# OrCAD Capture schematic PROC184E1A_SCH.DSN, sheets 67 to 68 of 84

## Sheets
67 72. POWER SUPPLY #1: size C; title: POWER SUPPLY #1; note: PROC184_SCH
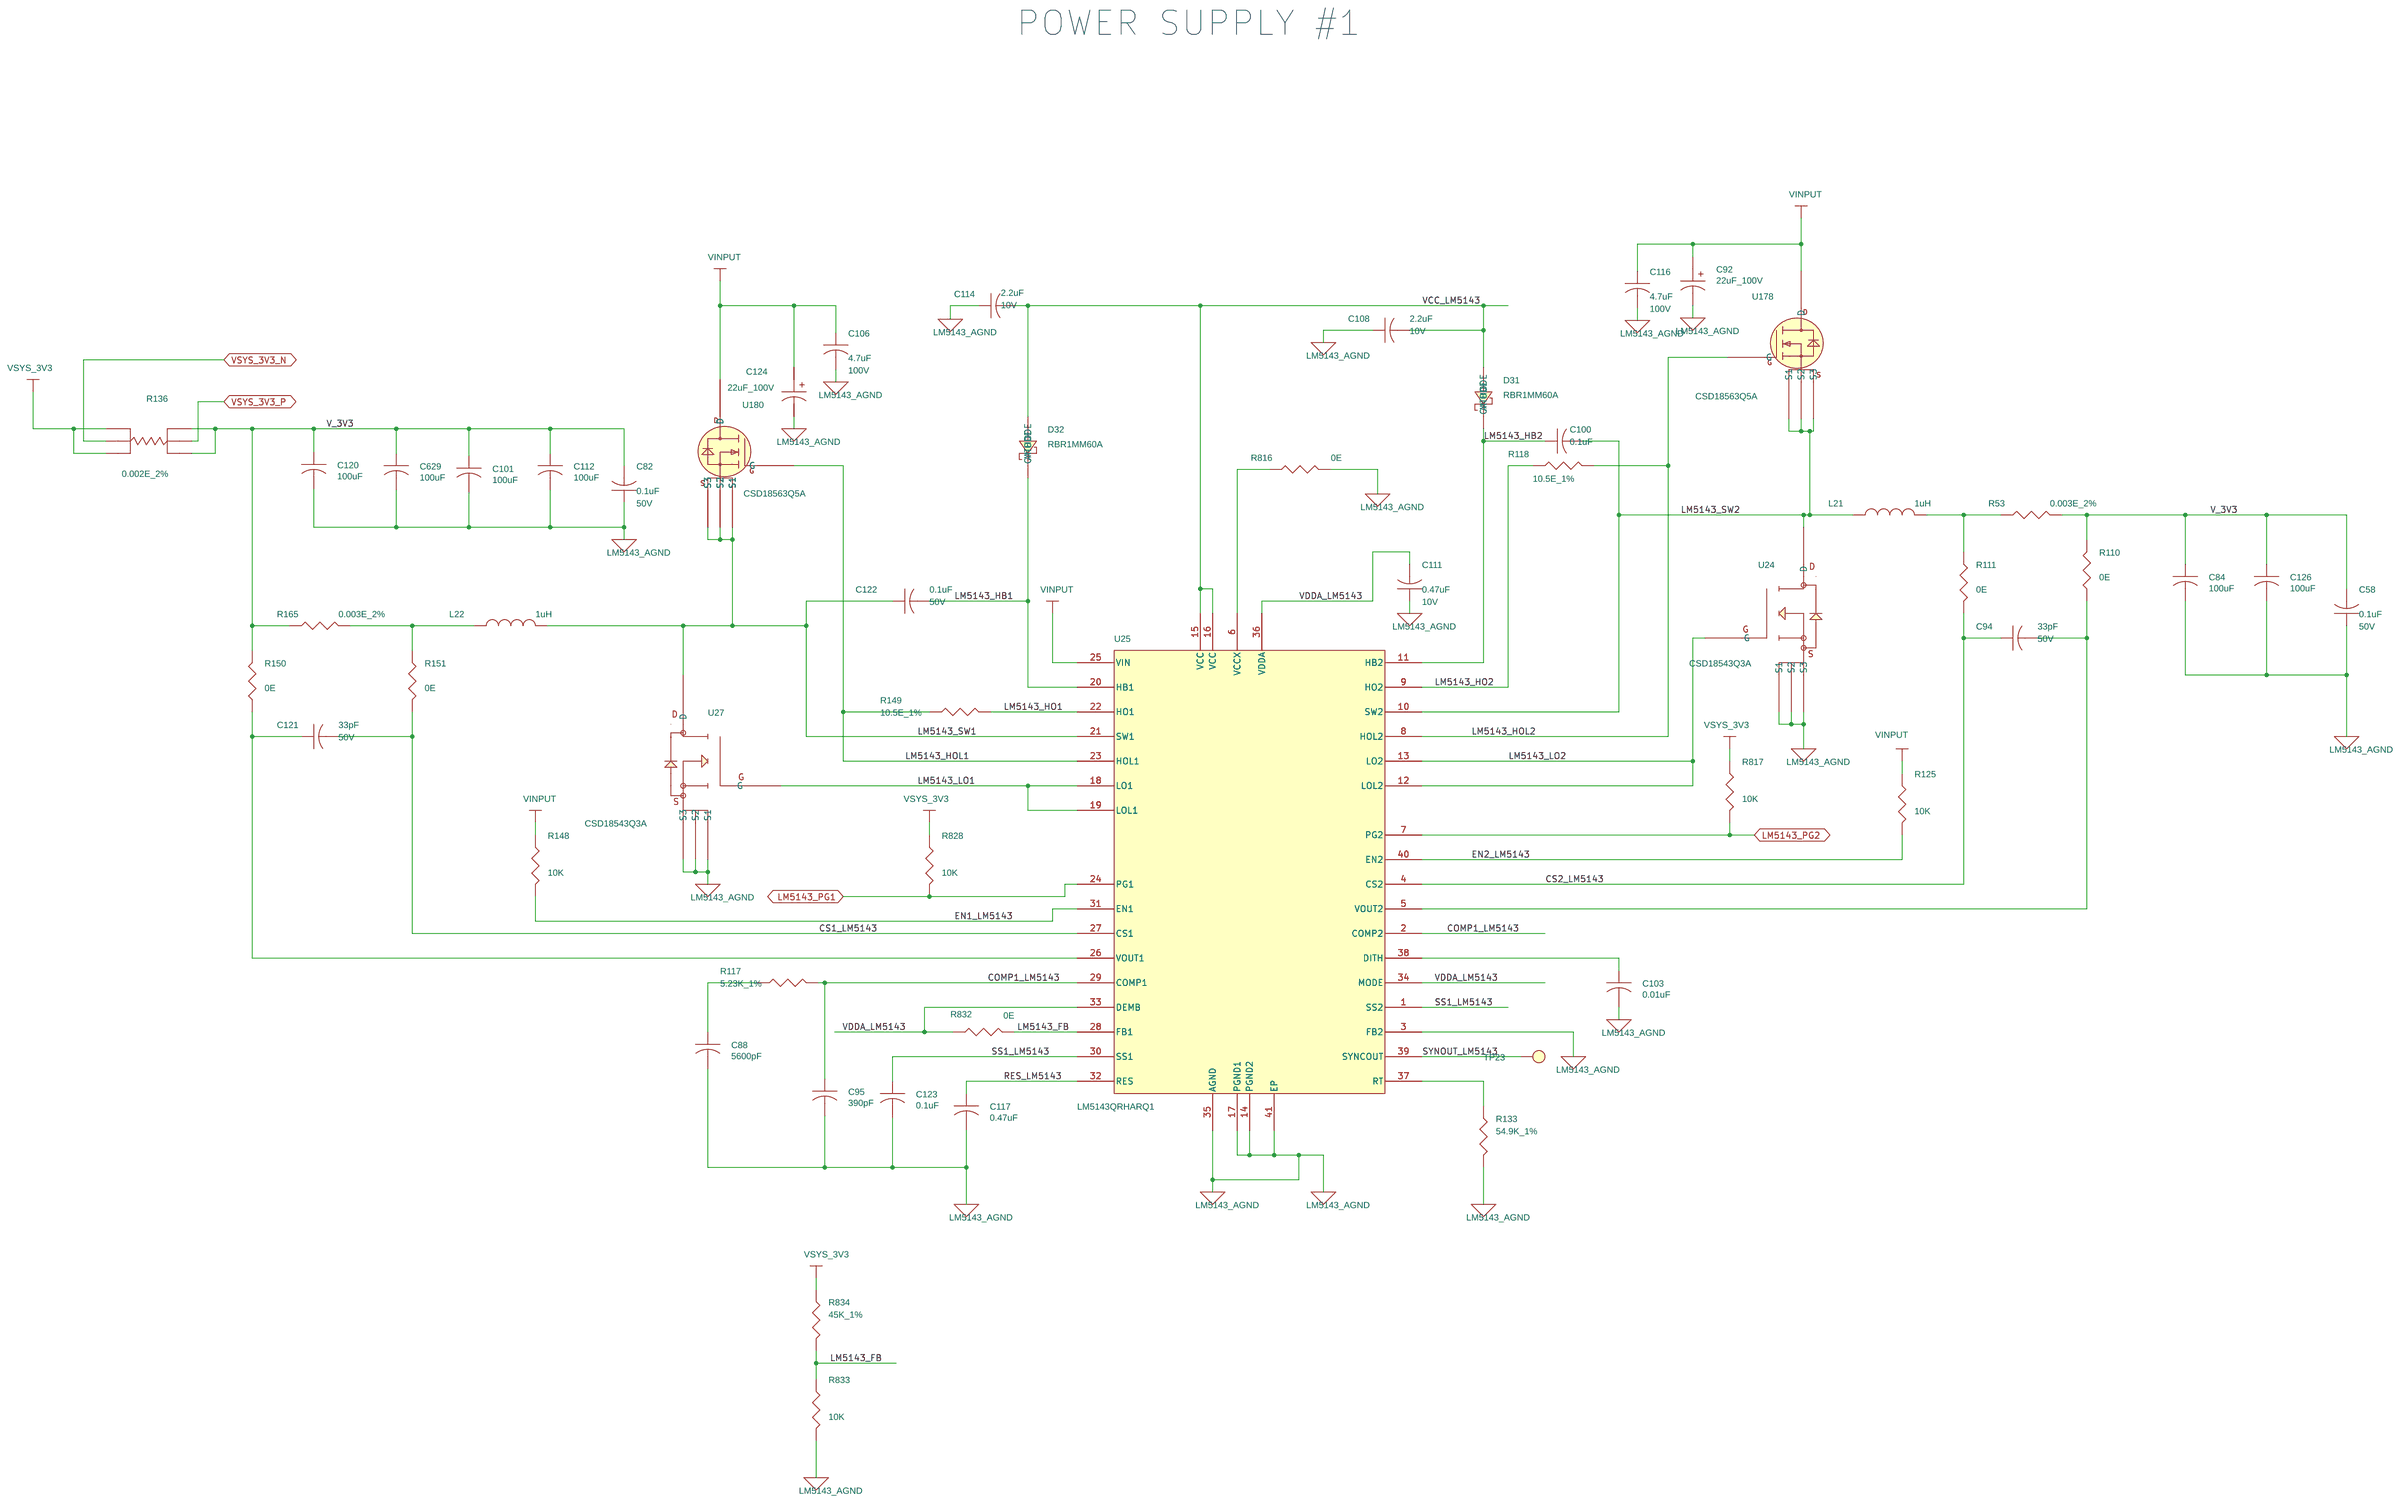
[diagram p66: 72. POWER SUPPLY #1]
68 75. POWER SUPPLY #4: size C; title: POWER SUPPLY #4; note: PROC184_SCH
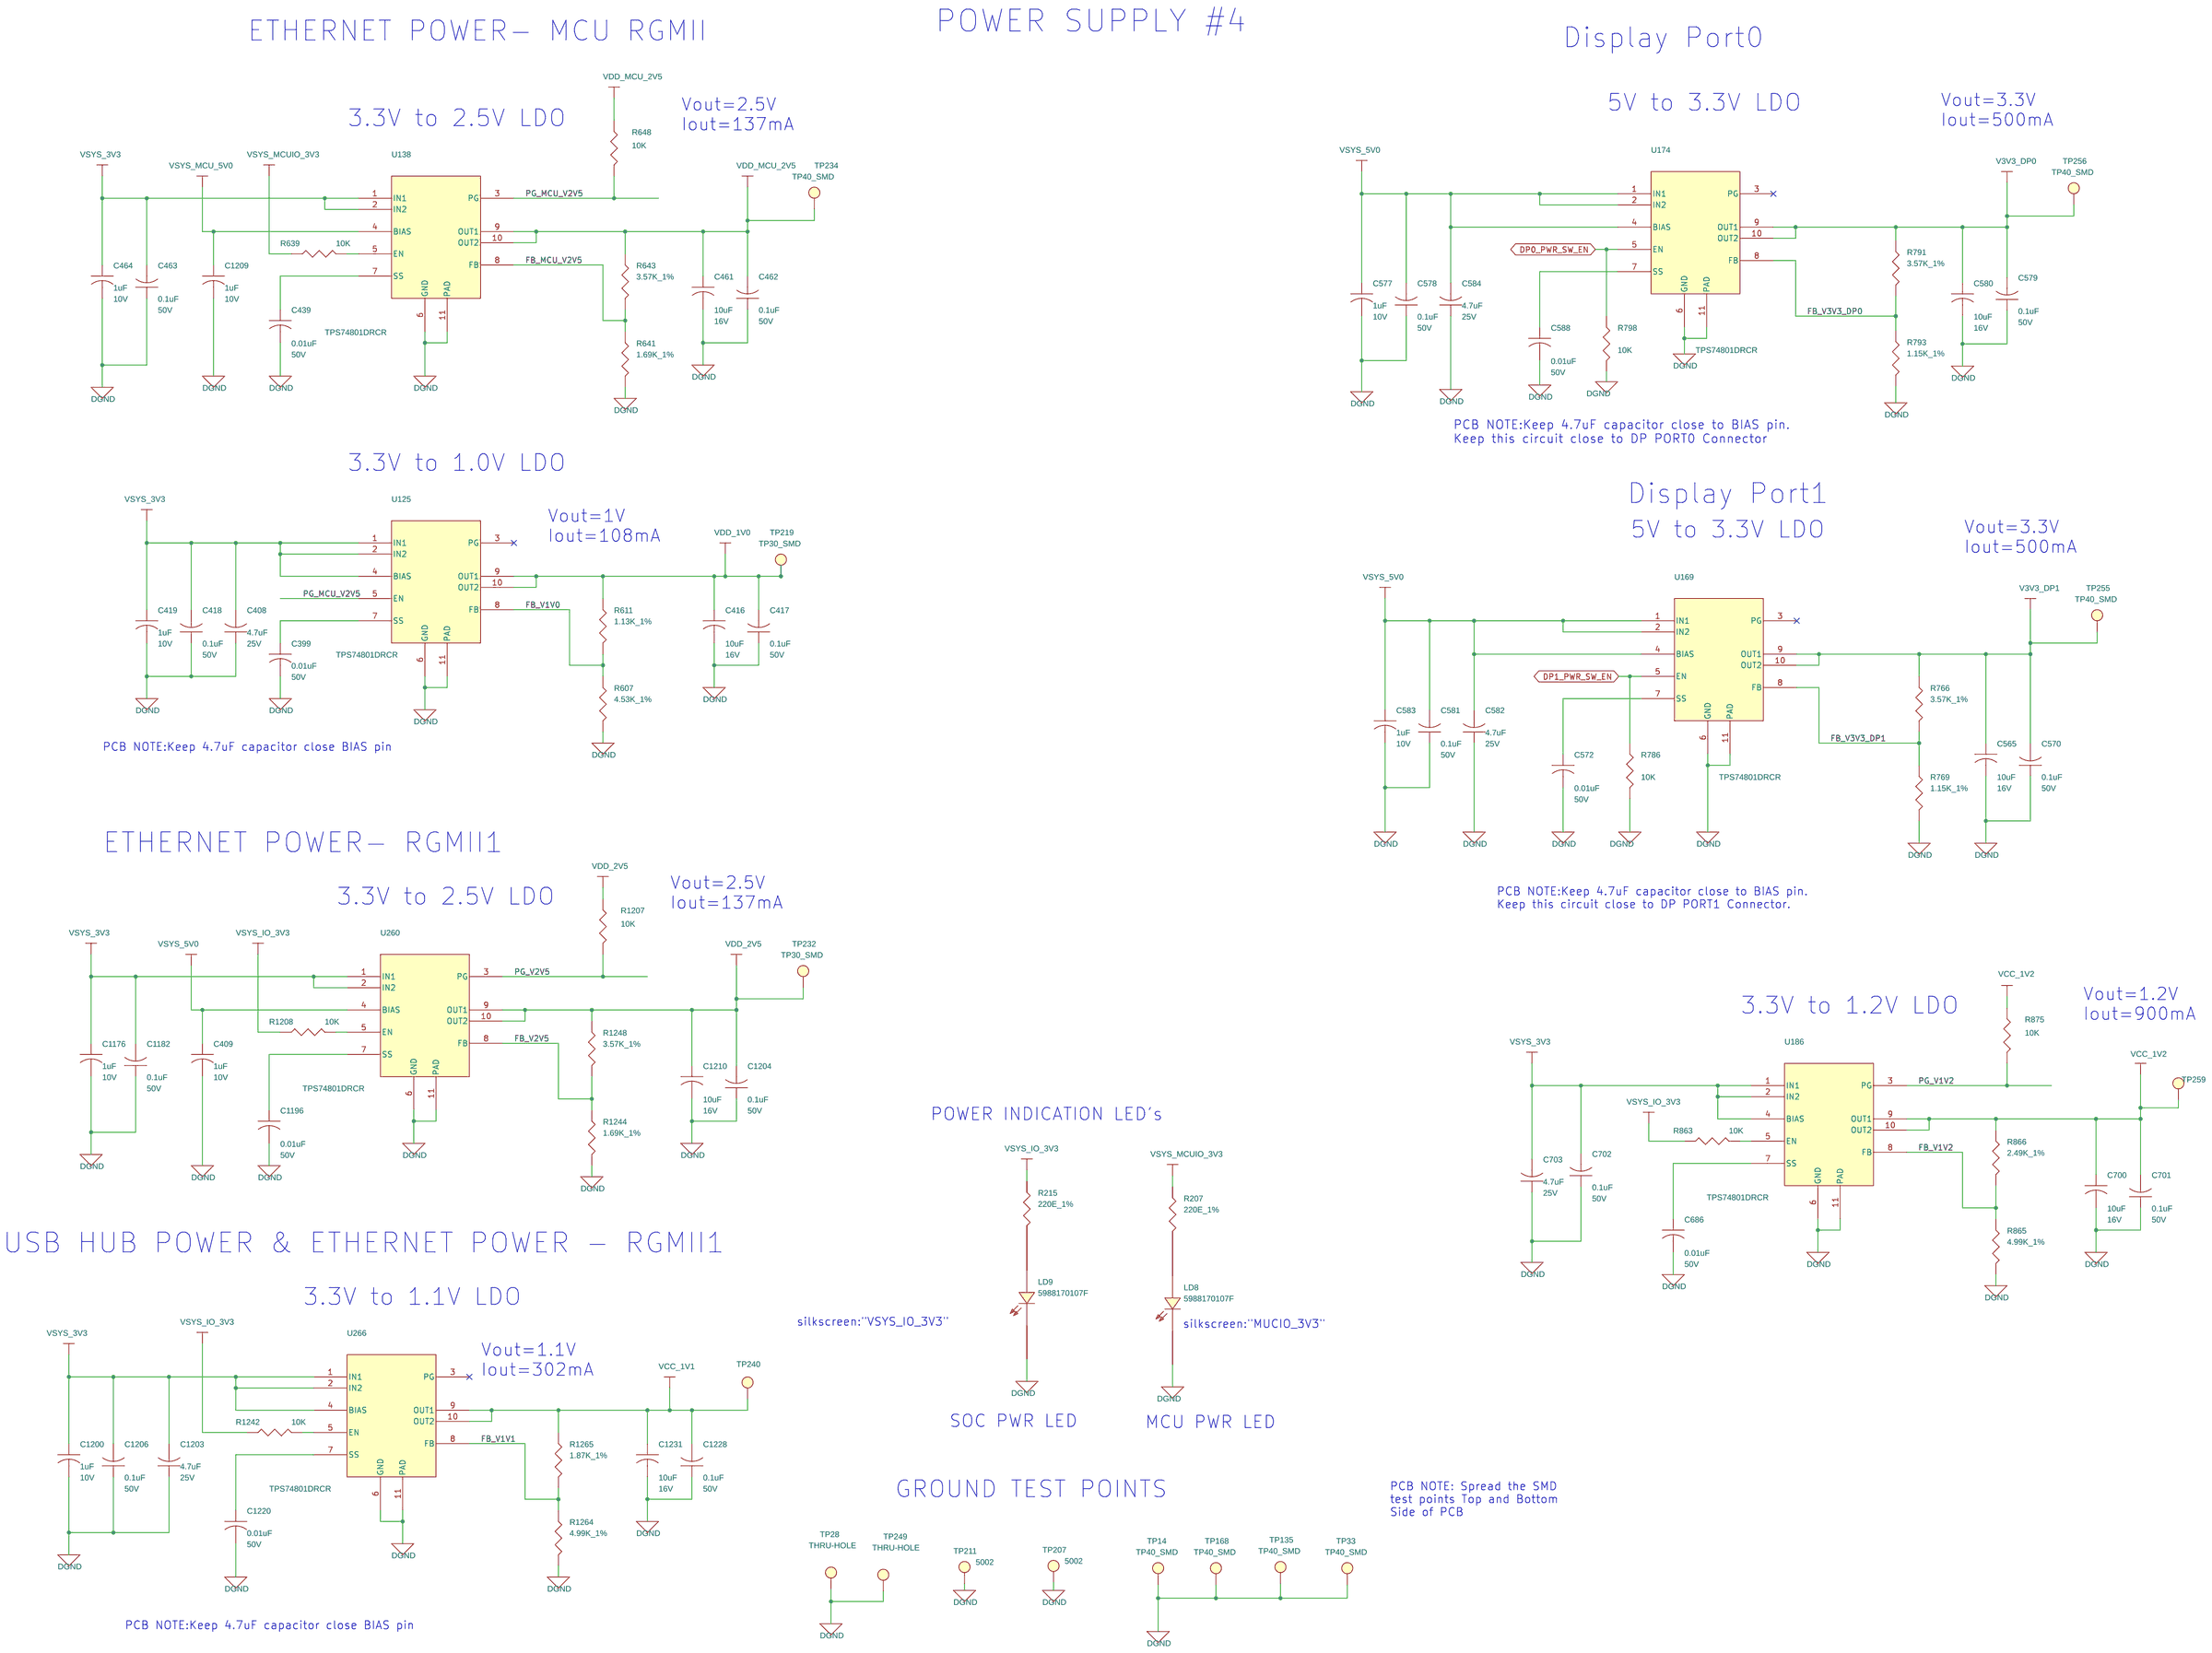
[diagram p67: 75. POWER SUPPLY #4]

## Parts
sheet 72. POWER SUPPLY #1
C58  0.1uF  [CAP0402_0-75]
C82  0.1uF  [CAP0402_0-75]
C84  100uF  [CAP1210_2-75]
C88  5600pF  [CAP0402_0-75]
C92  22uF_100V  [CAPAE_CASE8383_10-5]
C94  33pF  [CAP0402_0-75]
C95  390pF  [CAP0402_0-75]
C100  0.1uF  [CAP0402_0-75]
C101  100uF  [CAP1210_2-75]
C103  0.01uF  [CAP0402_0-75]
C106  4.7uF  [CAP1206_2]
C108  2.2uF  [CAP0402_0-75]
C111  0.47uF  [CAP0402_0-75]
C112  100uF  [CAP1210_2-75]
C114  2.2uF  [CAP0402_0-75]
C116  4.7uF  [CAP1206_2]
C117  0.47uF  [CAP0402_0-75]
C120  100uF  [CAP1210_2-75]
C121  33pF  [CAP0402_0-75]
C122  0.1uF  [CAP0402_0-75]
C123  0.1uF  [CAP0402_0-75]
C124  22uF_100V  [CAPAE_CASE8383_10-5]
C126  100uF  [CAP1210_2-75]
C629  100uF  [CAP1210_2-75]
D31  RBR1MM60A  [DIO_SOD123F_0-9]
D32  RBR1MM60A  [DIO_SOD123F_0-9]
L21  1uH  [IND_HLP5050CE-1R0-01_530X510_SMD_3-5]
L22  1uH  [IND_HLP5050CE-1R0-01_530X510_SMD_3-5]
R53  0.003E_2%  [RES1206_W_0-75]
R110  0E  [RES0402_0-5]
R111  0E  [RES0402_0-5]
R117  5.23K_1%  [RES0402_0-5]
R118  10.5E_1%  [RES0402_0-5]
R125  10K  [RES0402_0-5]
R133  54.9K_1%  [RES0402_0-5]
R136  0.002E_2%  [RES_FCSL90_3518-6_0-5_TI]
R148  10K  [RES0402_0-5]
R149  10.5E_1%  [RES0402_0-5]
R150  0E  [RES0402_0-5]
R151  0E  [RES0402_0-5]
R165  0.003E_2%  [RES1206_W_0-75]
R816  0E  [RES0402_0-5]
R817  10K  [RES0402_0-5]
R828  10K  [RES0402_0-5]
R832  0E  [RES0402_0-5]
R833  10K  [RES0402_0-5]
R834  45K_1%  [RES0402_0-5]
TP23  TP30_SMD  [TP30_SMD]
U24  CSD18543Q3A  [VSONP8_CSD18543Q_120X130_0-9]
U25  LM5143QRHARQ1  [QFN40_19-68_240X240_1_EP3-4]
U27  CSD18543Q3A  [VSONP8_CSD18543Q_120X130_0-9]
U178  CSD18563Q5A  [VSONP8_CSD19531_230X200_1-1]
U180  CSD18563Q5A  [VSONP8_CSD19531_230X200_1-1]
sheet 75. POWER SUPPLY #4
C399  0.01uF  [CAP0402_0-75]
C408  4.7uF  [CAP0603_1]
C409  1uF  [CAP0402_0-75]
C416  10uF  [CAP0805_1-5]
C417  0.1uF  [CAP0402_0-75]
C418  0.1uF  [CAP0402_0-75]
C419  1uF  [CAP0402_0-75]
C439  0.01uF  [CAP0402_0-75]
C461  10uF  [CAP0805_1-5]
C462  0.1uF  [CAP0402_0-75]
C463  0.1uF  [CAP0402_0-75]
C464  1uF  [CAP0402_0-75]
C565  10uF  [CAP0805_1-5]
C570  0.1uF  [CAP0402_0-75]
C572  0.01uF  [CAP0402_0-75]
C577  1uF  [CAP0402_0-75]
C578  0.1uF  [CAP0402_0-75]
C579  0.1uF  [CAP0402_0-75]
C580  10uF  [CAP0805_1-5]
C581  0.1uF  [CAP0402_0-75]
C582  4.7uF  [CAP0603_1]
C583  1uF  [CAP0402_0-75]
C584  4.7uF  [CAP0603_1]
C588  0.01uF  [CAP0402_0-75]
C686  0.01uF  [CAP0402_0-75]
C700  10uF  [CAP0805_1-5]
C701  0.1uF  [CAP0402_0-75]
C702  0.1uF  [CAP0402_0-75]
C703  4.7uF  [CAP0603_1]
C1176  1uF  [CAP0402_0-75]
C1182  0.1uF  [CAP0402_0-75]
C1196  0.01uF  [CAP0402_0-75]
C1200  1uF  [CAP0402_0-75]
C1203  4.7uF  [CAP0603_1]
C1204  0.1uF  [CAP0402_0-75]
C1206  0.1uF  [CAP0402_0-75]
C1209  1uF  [CAP0402_0-75]
C1210  10uF  [CAP0805_1-5]
C1220  0.01uF  [CAP0402_0-75]
C1228  0.1uF  [CAP0402_0-75]
C1231  10uF  [CAP0805_1-5]
LD8  5988170107F  [LED_0805_0-7]
LD9  5988170107F  [LED_0805_0-7]
R207  220E_1%  [RES0402_0-5]
R215  220E_1%  [RES0402_0-5]
R607  4.53K_1%  [RES0402_0-5]
R611  1.13K_1%  [RES0402_0-5]
R639  10K  [RES0402_0-5]
R641  1.69K_1%  [RES0402_0-5]
R643  3.57K_1%  [RES0402_0-5]
R648  10K  [RES0402_0-5]
R766  3.57K_1%  [RES0402_0-5]
R769  1.15K_1%  [RES0402_0-5]
R786  10K  [RES0402_0-5]
R791  3.57K_1%  [RES0402_0-5]
R793  1.15K_1%  [RES0402_0-5]
R798  10K  [RES0402_0-5]
R863  10K  [RES0402_0-5]
R865  4.99K_1%  [RES0402_0-5]
R866  2.49K_1%  [RES0402_0-5]
R875  10K  [RES0402_0-5]
R1207  10K  [RES0402_0-5]
R1208  10K  [RES0402_0-5]
R1242  10K  [RES0402_0-5]
R1244  1.69K_1%  [RES0402_0-5]
R1248  3.57K_1%  [RES0402_0-5]
R1264  4.99K_1%  [RES0402_0-5]
R1265  1.87K_1%  [RES0402_0-5]
TP14  TP40_SMD  [TP40_SMD]
TP28  THRU HOLE  [TP_40X65]
TP33  TP40_SMD  [TP40_SMD]
TP135  TP40_SMD  [TP40_SMD]
TP168  TP40_SMD  [TP40_SMD]
TP207  5002  [TP_CIR67D40_TH_4-6]
TP211  5002  [TP_CIR67D40_TH_4-6]
TP219  TP30_SMD  [TP30_SMD]
TP232  TP30_SMD  [TP30_SMD]
TP234  TP40_SMD  [TP40_SMD]
TP240  THRU HOLE  [TP_40X65]
TP249  THRU HOLE  [TP_40X65]
TP255  TP40_SMD  [TP40_SMD]
TP256  TP40_SMD  [TP40_SMD]
TP259  TP30_SMD  [TP30_SMD]
U125  TPS74801DRCR  [VSON10_TPS74801-Q1_120X120_1]
U138  TPS74801DRCR  [VSON10_TPS74801-Q1_120X120_1]
U169  TPS74801DRCR  [VSON10_TPS74801-Q1_120X120_1]
U174  TPS74801DRCR  [VSON10_TPS74801-Q1_120X120_1]
U186  TPS74801DRCR  [VSON10_TPS74801-Q1_120X120_1]
U260  TPS74801DRCR  [VSON10_TPS74801-Q1_120X120_1]
U266  TPS74801DRCR  [VSON10_TPS74801-Q1_120X120_1]

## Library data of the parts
C58 C82 C100 C122 C417 C418 C462 C463 C570 C578 C579 C581 C701 C702 C1182 C1204 C1206 C1228 = CAP: CAP CERAMIC 0.1uF 50V 10% X7R 0402; Automotive Alternate_mfr_name: TDK; Automotive Alternate_mfr_part_number: CGA2B3X7R1H104K050BB; Chkd/date: MANIRAJA/261020; Crtd /date: ALVY/211020; Custom_Duty: 15%; Customs_HS_Code: 85322990; Direct Alternate_mfr_name: TDK; Direct Alternate_mfr_part_number: C1005X7R1H104K050BE; Distributor_name: DIGIKEY; Distributor_part_number: 490-10700-1-ND; Footprint Path: Y:\MIS_DATABASE\Library\ALTIUM_TOOL\PCB_FOOTPRINTS\Altium_Footprint_Lib.PcbLib; Height: 0.55MM; Library Path: Y:\MIS_DATABASE\Library\ALTIUM_TOOL\SCHEMATICS_PARTS\MS_DISCRETE_Library.schlib; Manufacturer: MURATA; Mfr_name: MURATA; Mfr_part_number: GRM155R71H104KE14D; Mistral Part No: 120011100014-R; Package: 0402; Part_type: CAPACITORS\CERAMIC; Project: J7_CP; RoHS: RoHS; Temperature: -55°C+125°C; Tolerance: 10%; Voltage: 50V; Wattage: NA; Weight: 3.1mg; Datasheet: Y:\MIS_DATABASE\DATASHEETS\CAPACITORS\GRM155R71H104KE14.PDF
C84 C101 C112 C120 C126 C629 = CAP: CAP CERAMIC 100uF 6.3V 20% X5R AUTO 1210; Chkd/date: VASANTHA/290116; Crtd /date: VASANTHA/290116; Custom_Duty: 15%; Customs_HS_Code: 85322990; Distributor_name: DIGIKEY; Distributor_part_number: 490-12498-1-ND; Footprint Path: Y:\MIS_DATABASE\Library\ALTIUM_TOOL\PCB_FOOTPRINTS\Altium_Footprint_Lib.PcbLib; Height: 2.70MM; Library Path: Y:\MIS_DATABASE\Library\ALTIUM_TOOL\SCHEMATICS_PARTS\MS_DISCRETE_Library.schlib; Mfr_name: MURATA; Mfr_part_number: GRT32ER60J107ME13L; Mistral Part No: 120016010017-R; Package: 1210; Part_type: CAPACITORS\CERAMIC; Project: USHUS-2; RoHS: RoHS; Temperature: -55°C+85°C; Tolerance: 20%; Voltage: 6.3V; Wattage: NA; Weight: 16mg; Datasheet: Y:\MIS_DATABASE\DATASHEETS\CAPACITORS\GRT32ER60J107ME13L.PDF
C88 = CAP: CAP CERAMIC 5600pF 25V 10% X7R 0402; Chkd/date: ALVY/160222; Crtd /date: TAMILARASU/160222; Custom_Duty: 15%; Customs_HS_Code: 85322990; Distributor_name: DIGIKEY; Distributor_part_number: 478-10081-1-ND; Footprint Path: Y:\MIS_DATABASE\Library\ALTIUM_TOOL\PCB_FOOTPRINTS\Altium_Footprint_Lib.PcbLib; Height: 0.56MM; Library Path: Y:\MIS_DATABASE\Library\ALTIUM_TOOL\SCHEMATICS_PARTS\MS_DISCRETE_Library.schlib; Manufacturer: AVX CORPORATION; Mfr_name: AVX CORPORATION; Mfr_part_number: 04023C562KAT2A; Mistral Part No: 120015120009-R; Package: 0402; Part_type: CAPACITORS\CERAMIC; Project: TI_J7AHP_EVM_BRD; RoHS: RoHS; Temperature: -55°C+125°C; Tolerance: 10%; Voltage: 25V; Wattage: NA; Weight: 1.5mg; Datasheet: Y:\MIS_DATABASE\DATASHEETS\CAPACITORS\AVX_MLC.PDF
C92 C124 = CAP_POL: CAP ELECTROLYTIC 22uF 100V 20% CASE_8383; Chkd/date: ALVY/160222; Crtd /date: TAMILARASU/160222; Custom_Duty: 15%; Customs_HS_Code: 85322990; Distributor_name: DIGIKEY; Distributor_part_number: 493-6199-1-ND; Footprint Path: Y:\MIS_DATABASE\Library\ALTIUM_TOOL\PCB_FOOTPRINTS\Altium_Footprint_Lib.PcbLib; Height: 10.50MM; Library Path: Y:\MIS_DATABASE\Library\ALTIUM_TOOL\SCHEMATICS_PARTS\MS_DISCRETE_Library.schlib; Manufacturer: NICHICON; Mfr_name: NICHICON; Mfr_part_number: UUX2A220MNL6GS; Mistral Part No: 120022020014-R; Package: CASE_8383; Part_type: CAPACITORS\ELECTROLYTIC; Project: TI_J7AHP_EVM_BRD; RoHS: RoHS; Temperature: -55°C+105°C; Tolerance: 20%; Voltage: 100V; Wattage: NA; Weight: 800mg; Datasheet: Y:\MIS_DATABASE\DATASHEETS\CAPACITORS\UUX-SERIES.PDF
C94 C121 = CAP: CAP CERAMIC 33pF 50V 5% C0G(NP0) 0402; Assembly_Instruction: DNI; Chkd/date: NAVEED/260814; Crtd /date: BAVISH/080611; Custom_Duty: 15%; Customs_HS_Code: 85322990; Distributor_name: DIGIKEY; Distributor_part_number: 490-3220-1-ND; Footprint Path: Y:\MIS_DATABASE\Library\ALTIUM_TOOL\PCB_FOOTPRINTS\Altium_Footprint_Lib.PcbLib; Height: 0.55MM; Library Path: Y:\MIS_DATABASE\Library\ALTIUM_TOOL\SCHEMATICS_PARTS\MS_DISCRETE_Library.schlib; Manufacturer: MURATA; Mfr_name: MURATA; Mfr_part_number: GRM1555C1H330JZ01D; Mistral Part No: 120009030395-R; Package: 0402; Part_type: CAPACITORS\CERAMIC; Project: ACRO_DM3730; RoHS: RoHS; Temperature: -55°C+125°C; Tolerance: 5%; Voltage: 50V; Wattage: NA; Weight: 6mg; Datasheet: Y:\MIS_DATABASE\DATASHEETS\CAPACITORS\MURATA-GXX-SER_NOV17.PDF
C95 = CAP: CAP CERAMIC 390pF 50V 5% X7R 0402; Chkd/date: SHREESHAIL/100807; Crtd /date: MAZHAR/090807; Custom_Duty: 15%; Customs_HS_Code: 85322990; Distributor_name: DIGIKEY; Distributor_part_number: 478-5269-1-ND; Footprint Path: Y:\MIS_DATABASE\Library\ALTIUM_TOOL\PCB_FOOTPRINTS\Altium_Footprint_Lib.PcbLib; Height: 0.56MM; Library Path: Y:\MIS_DATABASE\Library\ALTIUM_TOOL\SCHEMATICS_PARTS\MS_DISCRETE_Library.schlib; Manufacturer: AVX CORPORATION; Mfr_name: AVX CORPORATION; Mfr_part_number: 04025C391JAT2A; Mistral Part No: 120009030403-R; Package: 0402; Part_type: CAPACITORS\CERAMIC; Project: TELEMETRY ENCODER; RoHS: RoHS; Temperature: -55°C+125°C; Tolerance: 5%; Voltage: 50V; Wattage: NA; Weight: 0.65mg; Datasheet: Y:\MIS_DATABASE\DATASHEETS\CAPACITORS\AVX_MLC.PDF
C103 = CAP: CAP CERAMIC 0.01uF 50V 10% X7R 0402; Chkd/date: MANIRAJA/280319; Crtd /date: MANIRAJA/280319; Custom_Duty: 15%; Customs_HS_Code: 85322990; Distributor_name: DIGIKEY; Distributor_part_number: 490-4516-1-ND; Footprint Path: Y:\MIS_DATABASE\Library\ALTIUM_TOOL\PCB_FOOTPRINTS\Altium_Footprint_Lib.PcbLib; Height: 0.55MM; Library Path: Y:\MIS_DATABASE\Library\ALTIUM_TOOL\SCHEMATICS_PARTS\MS_DISCRETE_Library.schlib; Manufacturer: MURATA; Mfr_name: MURATA; Mfr_part_number: GRM155R71H103KA88D; Mistral Part No: 120009030025-R; Package: 0402; Part_type: CAPACITORS\CERAMIC; Project: G4_SVGA; RoHS: RoHS; Temperature: -55°C+125°C; Tolerance: 10%; Voltage: 50V; Wattage: NA; Weight: 0.65mg; Datasheet: Y:\MIS_DATABASE\DATASHEETS\CAPACITORS\GRM155R71H103KA88D.PDF
C106 C116 = CAP: CAP CERAMIC 4.7uF 100V 10% X7S 1206; Automotive Alternate_mfr_name: TDK; Automotive Alternate_mfr_part_number: CGA4J1X7R1H475K125AC; Chkd/date: MANIRAJA/121020; Crtd /date: ALVY/091020; Custom_Duty: 15%; Customs_HS_Code: 85322990; Direct Alternate_mfr_name: MURATA; Direct Alternate_mfr_part_number: GRM21BR61H475KE51L; Distributor_name: DIGIKEY; Distributor_part_number: 490-18620-1-ND; Footprint Path: Y:\MIS_DATABASE\Library\ALTIUM_TOOL\PCB_FOOTPRINTS\Altium_Footprint_Lib.PcbLib; Height: 1.90MM; Library Path: Y:\MIS_DATABASE\Library\ALTIUM_TOOL\SCHEMATICS_PARTS\MS_DISCRETE_Library.schlib; Manufacturer: MURATA; Mfr_name: MURATA; Mfr_part_number: GRM31CC72A475KE11L; Mistral Part No: 120020100021-R; Package: 1206; Part_type: CAPACITORS\CERAMIC; Project: ECU_RO; RoHS: RoHS; Temperature: -55°C+125°C; Tolerance: 10%; Voltage: 100V; Wattage: NA; Weight: 64mg; Datasheet: Y:\MIS_DATABASE\DATASHEETS\CAPACITORS\GRM31CC72A475KE11.PDF
C108 C114 = CAP: CAP CERAMIC 2.2uF 10V 10% X5R 0402; Automotive Alternate_mfr_name: TAIYO YUDEN; Automotive Alternate_mfr_part_number: EMK105BJ105KVHF; Chkd/date: MANIRAJA/251120; Crtd /date: ALVY/241120; Custom_Duty: 15%; Customs_HS_Code: 85322990; Direct Alternate_mfr_name: YAGEO AMERICA; Direct Alternate_mfr_part_number: CC0402KRX5R7BB105; Distributor_name: MOUSER; Distributor_part_number: 81-GRM155R61A225K01D; Footprint Path: Y:\MIS_DATABASE\Library\ALTIUM_TOOL\PCB_FOOTPRINTS\Altium_Footprint_Lib.PcbLib; Height: 0.55MM; Library Path: Y:\MIS_DATABASE\Library\ALTIUM_TOOL\SCHEMATICS_PARTS\MS_DISCRETE_Library.schlib; Manufacturer: TDK CORPORATION; Mfr_name: MURATA; Mfr_part_number: GRM155R61A225KE01D; Mistral Part No: 120011100038-R; Package: 0402; Part_type: CAPACITORS\CERAMIC; Project: PLCC_DIGITAL BRD PROTO; RoHS: RoHS; Temperature: -55°C+85°C; Tolerance: 10%; Voltage: 10V; Wattage: NA; Weight: 1.6mg; Datasheet: Y:\MIS_DATABASE\DATASHEETS\CAPACITORS\MURATA-GXX-SER_NOV17.PDF
C111 = CAP: CAP CERAMIC 0.47uF 10V 10% X7S AUTO 0402; Automotive Alternate_mfr_name: TAIYO YUDEN; Automotive Alternate_mfr_part_number: EMK105BJ105KVHF; Chkd/date: MANIRAJA/280918; Crtd /date: ALVY/280918; Custom_Duty: 15%; Customs_HS_Code: 85322990; Direct Alternate_mfr_name: YAGEO AMERICA; Direct Alternate_mfr_part_number: CC0402KRX5R7BB105; Distributor_name: DIGIKEY; Distributor_part_number: 490-14427-1-ND; Footprint Path: Y:\MIS_DATABASE\Library\ALTIUM_TOOL\PCB_FOOTPRINTS\Altium_Footprint_Lib.PcbLib; Height: 0.60MM; Library Path: Y:\MIS_DATABASE\Library\ALTIUM_TOOL\SCHEMATICS_PARTS\MS_DISCRETE_Library.schlib; Manufacturer: TDK CORPORATION; Mfr_name: MURATA; Mfr_part_number: GCM155C71A474KE36D; Mistral Part No: 120018090057-R; Package: 0402; Part_type: CAPACITORS\CERAMIC; Project: TI_J7_SVB-DUT; RoHS: RoHS; Temperature: -55°C+125°C; Tolerance: 10%; Voltage: 10V; Wattage: NA; Weight: 6mg; Datasheet: Y:\MIS_DATABASE\DATASHEETS\CAPACITORS\GCM155C71A474KE36D.PDF
C117 = CAP: CAP CERAMIC 0.47uF 10V 10% X7S AUTO 0402; Chkd/date: MANIRAJA/280918; Crtd /date: ALVY/280918; Custom_Duty: 15%; Customs_HS_Code: 85322990; Distributor_name: DIGIKEY; Distributor_part_number: 490-14427-1-ND; Footprint Path: Y:\MIS_DATABASE\Library\ALTIUM_TOOL\PCB_FOOTPRINTS\Altium_Footprint_Lib.PcbLib; Height: 0.60MM; Library Path: Y:\MIS_DATABASE\Library\ALTIUM_TOOL\SCHEMATICS_PARTS\MS_DISCRETE_Library.schlib; Manufacturer: MURATA; Mfr_name: MURATA; Mfr_part_number: GCM155C71A474KE36D; Mistral Part No: 120018090057-R; Package: 0402; Part_type: CAPACITORS\CERAMIC; Project: TI_J7_SVB-DUT; RoHS: RoHS; Temperature: -55°C+125°C; Tolerance: 10%; Voltage: 10V; Wattage: NA; Weight: 6mg; Datasheet: Y:\MIS_DATABASE\DATASHEETS\CAPACITORS\GCM155C71A474KE36D.PDF
C123 = CAP: CAP CERAMIC 0.1uF 50V 10% X7R 0402; Chkd/date: MANIRAJA/261020; Crtd /date: ALVY/211020; Custom_Duty: 15%; Customs_HS_Code: 85322990; Distributor_name: DIGIKEY; Distributor_part_number: 490-10700-1-ND; Footprint Path: Y:\MIS_DATABASE\Library\ALTIUM_TOOL\PCB_FOOTPRINTS\Altium_Footprint_Lib.PcbLib; Height: 0.55MM; Library Path: Y:\MIS_DATABASE\Library\ALTIUM_TOOL\SCHEMATICS_PARTS\MS_DISCRETE_Library.schlib; Manufacturer: MURATA; Mfr_name: MURATA; Mfr_part_number: GRM155R71H104KE14D; Mistral Part No: 120011100014-R; Package: 0402; Part_type: CAPACITORS\CERAMIC; Project: J7_CP; RoHS: RoHS; Temperature: -55°C+125°C; Tolerance: 10%; Voltage: 50V; Wattage: NA; Weight: 3.1mg; Datasheet: Y:\MIS_DATABASE\DATASHEETS\CAPACITORS\GRM155R71H104KE14.PDF
D31 D32 = DIODE_SCHOTTKY: DIODE SCHOTTKY RECTIFIER 60V 1A SOD-123FL; Chkd/date: ALVY/240322; Crtd /date: TAMILARASU/220322; Custom_Duty: 15%; Customs_HS_Code: 85412900; Distributor_name: DIGIKEY; Distributor_part_number: RBR1MM60ACT-ND; Footprint Path: Y:\MIS_DATABASE\Library\ALTIUM_TOOL\PCB_FOOTPRINTS\Altium_Footprint_Lib.PcbLib; Height: 0.90MM; Library Path: Y:\MIS_DATABASE\Library\ALTIUM_TOOL\SCHEMATICS_PARTS\MS_DISCRETE_Library.schlib; Manufacturer: ROHM; Mfr_name: ROHM; Mfr_part_number: RBR1MM60ATR; Mistral Part No: 130022030051-R; Package: SOD-123FL; Part_type: DIODE\SCHOTTKY; Project: TI_J7AHP_EVM_BRD; RoHS: RoHS; Temperature: NA; Tolerance: NA; Voltage: 60V; Wattage: NA; Weight: 27.827mg; Datasheet: Y:\MIS_DATABASE\DATASHEETS\DISCRETES\DIODES\RBR1MM60A.PDF
L21 L22 = INDUCTOR: IND POWER 1uH 24A 20% SMD; Chkd/date: ALVY/110320; Crtd /date: ALVY/110320; Custom_Duty: 24%; Customs_HS_Code: 85437099; Distributor_name: DIGIKEY; Distributor_part_number: 541-1017-1-ND; Footprint Path: Y:\MIS_DATABASE\Library\ALTIUM_TOOL\PCB_FOOTPRINTS\Altium_Footprint_Lib.PcbLib; Height: 3.50MM; Library Path: Y:\MIS_DATABASE\Library\ALTIUM_TOOL\SCHEMATICS_PARTS\MS_DISCRETE_Library.schlib; Manufacturer: VISHAY; Mfr_name: VISHAY; Mfr_part_number: IHLP5050CEER1R0M01; Mistral Part No: 130020030017-R; Package: SMD; Project: TI_J7ES_CP; RoHS: RoHS; Temperature: -55°C+125°C; Tolerance: 20%; Voltage: NA; Wattage: NA; Weight: NA; Datasheet: Y:\MIS_DATABASE\DATASHEETS\DISCRETES\INDUCTORS\IHLP5050CE-01-SER.PDF
R53 R165 = RESISTOR: RES CURRENT SENSE 0.003E 1.5W 2% 0612; Chkd/date: ALVY/110320; Crtd /date: ALVY/110320; Custom_Duty: 15%; Customs_HS_Code: 85332119; Distributor_name: DIGIKEY; Distributor_part_number: FCSL32R003GERCT-ND; Footprint Path: Y:\MIS_DATABASE\Library\ALTIUM_TOOL\PCB_FOOTPRINTS\Altium_Footprint_Lib.PcbLib; Height: 0.60MM; Library Path: Y:\MIS_DATABASE\Library\ALTIUM_TOOL\SCHEMATICS_PARTS\MS_DISCRETE_Library.schlib; Manufacturer: OHMITE; Mfr_name: OHMITE; Mfr_part_number: FCSL32R003GER; Mistral Part No: 110020030026-R; Package: 0612; Part_type: RESISTORS\FIXED; Project: TI_J7ES_CP; RoHS: RoHS; Temperature: -55°C+155°C; Tolerance: 2%; Voltage: NA; Wattage: 1.5W; Weight: 30mg; Datasheet: Y:\MIS_DATABASE\DATASHEETS\RESISTORS\FCSL-SER.PDF
R110 R111 R150 R151 R816 R832 = RESISTOR: RES 0E 1/10W JUMPER 0402; Chkd/date: VASANTHA/061216; Crtd /date: NAVEED/201014; Custom_Duty: 15%; Customs_HS_Code: 85332119; Distributor_name: DIGIKEY; Distributor_part_number: P0.0JCT-ND; Footprint Path: Y:\MIS_DATABASE\Library\ALTIUM_TOOL\PCB_FOOTPRINTS\Altium_Footprint_Lib.PcbLib; Height: 0.40MM; IBISSP_MODLES: VALUE REPEATING 2 TIME; Library Path: Y:\MIS_DATABASE\Library\ALTIUM_TOOL\SCHEMATICS_PARTS\MS_DISCRETE_Library.schlib; Manufacturer: PANASONIC-ECG; Mfr_name: PANASONIC-ECG; Mfr_part_number: ERJ-2GE0R00X; Mistral Part No: 110018030052-R; Package: 0402; Part_type: RESISTORS\FIXED; Project: AEGIS POM; RoHS: RoHS; Temperature: -55°C+155°C; Tolerance: NA; Voltage: NA; Wattage: 1/10W; Weight: 0.8mg; Datasheet: Y:\MIS_DATABASE\DATASHEETS\RESISTORS\PAN-ERJSER_NOV17.PDF
R117 = RESISTOR: RES 5.23K 1/16W 1% 0402; Chkd/date: JEBRAN/110815; Crtd /date: JEBRAN/110815; Custom_Duty: 15%; Customs_HS_Code: 85332119; Distributor_name: DIGIKEY; Distributor_part_number: 541-5.23KLCT-ND; Footprint Path: Y:\MIS_DATABASE\Library\ALTIUM_TOOL\PCB_FOOTPRINTS\Altium_Footprint_Lib.PcbLib; Height: 0.40MM; Library Path: Y:\MIS_DATABASE\Library\ALTIUM_TOOL\SCHEMATICS_PARTS\MS_DISCRETE_Library.schlib; Manufacturer: VISHAY; Mfr_name: VISHAY; Mfr_part_number: CRCW04025K23FKED; Mistral Part No: 110015080018-R; Package: 0402; Part_type: RESISTORS\FIXED; Project: OCTASIC_3000; RoHS: RoHS; Temperature: -55°C+155°C; Tolerance: 1%; Voltage: NA; Wattage: 1/16W; Weight: 0.65mg; Datasheet: Y:\MIS_DATABASE\DATASHEETS\RESISTORS\CRCW0603.PDF
R118 R149 = RESISTOR: RES 10.5E 1/16W 1% 0402; Chkd/date: MANIRAJA/110918; Crtd /date: ALVY/110918; Custom_Duty: 15%; Customs_HS_Code: 85332119; Distributor_name: DIGIKEY; Distributor_part_number: 541-10.5LCT-ND; Footprint Path: Y:\MIS_DATABASE\Library\ALTIUM_TOOL\PCB_FOOTPRINTS\Altium_Footprint_Lib.PcbLib; Height: 0.40MM; Library Path: Y:\MIS_DATABASE\Library\ALTIUM_TOOL\SCHEMATICS_PARTS\MS_DISCRETE_Library.schlib; Manufacturer: VISHAY; Mfr_name: VISHAY; Mfr_part_number: CRCW040210R5FKED; Mistral Part No: 110018090012-R; Package: 0402; Part_type: RESISTORS\FIXED; Project: TI_J7ES_EVM_CP; RoHS: RoHS; Temperature: -55°C+155°C; Tolerance: 1%; Voltage: NA; Wattage: 1/16W; Weight: 0.65mg; Datasheet: Y:\MIS_DATABASE\DATASHEETS\RESISTORS\CRCW0603.PDF
R125 R148 R639 R648 R786 R798 R817 R828 R833 R863 R875 R1207 R1208 R1242 = RESISTOR: RES 10K 1/16W 5% 0402; Chkd/date: VASANTHA/061216; Crtd /date: MAZHAR/230805; Custom_Duty: 15%; Customs_HS_Code: 85332119; Distributor_name: DIGIKEY; Distributor_part_number: 311-10KJRCT-ND; Footprint Path: Y:\MIS_DATABASE\Library\ALTIUM_TOOL\PCB_FOOTPRINTS\Altium_Footprint_Lib.PcbLib; Height: 0.40MM; Library Path: Y:\MIS_DATABASE\Library\ALTIUM_TOOL\SCHEMATICS_PARTS\MS_DISCRETE_Library.schlib; Manufacturer: YAGEO AMERICA; Mfr_name: YAGEO AMERICA; Mfr_part_number: RC0402JR-0710KL; Mistral Part No: 110011060021-R; Package: 0402; Part_type: RESISTORS\FIXED; Project: HSE; RoHS: RoHS; Temperature: -55°C+155°C; Tolerance: 5%; Voltage: NA; Wattage: 1/16W; Weight: 0.65mg; Datasheet: Y:\MIS_DATABASE\DATASHEETS\RESISTORS\RCXXXXL-SER_MAR18.PDF
R133 = RESISTOR: RES 54.9K 1/16W 1% 0402; Chkd/date: MANIRAJA/121020; Crtd /date: ALVY/091020; Custom_Duty: 15%; Customs_HS_Code: 85332119; Distributor_name: DIGIKEY; Distributor_part_number: 541-54.9KLCT-ND; Footprint Path: Y:\MIS_DATABASE\Library\ALTIUM_TOOL\PCB_FOOTPRINTS\Altium_Footprint_Lib.PcbLib; Height: 0.40MM; Library Path: Y:\MIS_DATABASE\Library\ALTIUM_TOOL\SCHEMATICS_PARTS\MS_DISCRETE_Library.schlib; Manufacturer: VISHAY; Mfr_name: VISHAY; Mfr_part_number: CRCW040254K9FKED; Mistral Part No: 110017100006-R; Package: 0402; Part_type: RESISTORS\FIXED; Project: HSAD_PRDN_VER1; RoHS: RoHS; Temperature: -55°C+155°C; Tolerance: 1%; Voltage: NA; Wattage: 1/16W; Weight: 0.65mg; Datasheet: Y:\MIS_DATABASE\DATASHEETS\RESISTORS\CRCW0603.PDF
R136 = RESISTOR_KRL_TI: RES CURRENT SENSE 0.002E 4W 2% 1835; Chkd/date: ALVY/220222; Crtd /date: TAMILARASU/220222; Custom_Duty: 15%; Customs_HS_Code: 85332119; Distributor_name: DIGIKEY; Distributor_part_number: FCSL90R002GERCT-ND; Footprint Path: Y:\MIS_DATABASE\Library\ALTIUM_TOOL\PCB_FOOTPRINTS\Altium_Footprint_Lib.PcbLib; Height: 0.50MM; Library Path: Y:\MIS_DATABASE\Library\ALTIUM_TOOL\SCHEMATICS_PARTS\MS_DISCRETE_Library.schlib; Mfr_name: OHMITE; Mfr_part_number: FCSL90R002GER_TI; Mistral Part No: 110022020013-R; Package: 1835; Part_type: RESISTORS\FIXED; Project: TI_J7AHP_EVM_BRD; RoHS: RoHS; Temperature: -55°C+155°C; Tolerance: 2%; Voltage: NA; Wattage: 4W; Weight: 170mg; Datasheet: Y:\MIS_DATABASE\DATASHEETS\RESISTORS\FCSL-TI-SER.PDF
R834 = RESISTOR: RES 45K 1/16W 1% 0402; Chkd/date: MANIRAJA/010719; Crtd /date: ALVY/010719; Custom_Duty: 15%; Customs_HS_Code: 85332119; Distributor_name: DIGIKEY; Distributor_part_number: RC0402FR-0745KL-ND; Footprint Path: Y:\MIS_DATABASE\Library\ALTIUM_TOOL\PCB_FOOTPRINTS\Altium_Footprint_Lib.PcbLib; Height: 0.40MM; Library Path: Y:\MIS_DATABASE\Library\ALTIUM_TOOL\SCHEMATICS_PARTS\MS_DISCRETE_Library.schlib; Mfr_name: YAGEO AMERICA; Mfr_part_number: RC0402FR-0745KL; Mistral Part No: 110019070005-R; Package: 0402; Part_type: RESISTORS\FIXED; Project: MYTHIC_FORMFACTOR_BRD; RoHS: RoHS; Temperature: -55°C+155°C; Tolerance: 1%; Voltage: NA; Wattage: 1/16W; Weight: NA; Datasheet: Y:\MIS_DATABASE\DATASHEETS\RESISTORS\RCXXXXL-SER_MAR18.PDF
TP23 TP219 TP232 TP259 = TESTPOINT: TESTPOINT CIR 30 SMD; Chkd/date: SHREESHAIL/171006; Crtd /date: MAZHAR/171006; Custom_Duty: NA; Customs_HS_Code: NA; Distributor_name: NA; Distributor_part_number: NA; Footprint Path: Y:\MIS_DATABASE\Library\ALTIUM_TOOL\PCB_FOOTPRINTS\Altium_Footprint_Lib.PcbLib; Height: NA; Library Path: Y:\MIS_DATABASE\Library\ALTIUM_TOOL\SCHEMATICS_PARTS\MS_DISCRETE_Library.schlib; MECHANICAL 3D STEP FILE: NA; Manufacturer: LOCAL; Mfr_name: LOCAL; Mistral Part No: 130009030930; Package: SMD; Project: BT MODULE_CSRBC04; RoHS: NA; Temperature: NA; Tolerance: NA; Voltage: NA; Wattage: NA; Weight: NA; Datasheet: NA
U24 U27 = MOSFET_CSD18501Q5A_TI: IC MOSFET N-CHANNEL 60V VSONP8; Chkd/date: MANIRAJA/041017; Crtd /date: MANIRAJA/041017; Custom_Duty: 15%; Customs_HS_Code: 85423100; Distributor_name: DIGIKEY; Distributor_part_number: 296-47321-1-ND; Footprint Path: Y:\MIS_DATABASE\Library\ALTIUM_TOOL\PCB_FOOTPRINTS\Altium_Footprint_Lib.PcbLib; Height: 0.90MM; Library Path: Y:\MIS_DATABASE\Library\ALTIUM_TOOL\SCHEMATICS_PARTS\MS_MOSFET_Library.schlib; Library Ref: MOSFET_CSD18501Q5A; Manufacturer: TEXAS INSTRUMENTS; Mfr_name: TEXAS INSTRUMENTS; Mistral Part No: 142017100004-R; Package: VSONP8; Part_type: ICS\POWER\MOSFET; Project: TI_MAXIE_CPB; RoHS: RoHS; Temperature: -55°C+150°C; Tolerance: NA; Voltage: 60V; Wattage: NA; Weight: NA; Datasheet: Y:\MIS_DATABASE\DATASHEETS\ICS\POWER\CSD18543Q3A.PDF
U25 = LM5143-Q1_VQFNP40: IC 3.5V-65V DUAL SYNCHRONOUS BUCK DC/DC CONTROLLER WITH ULTRA-LOW IQ VQFNP40; Chkd/date: MANIRAJA/110222; Crtd /date: ALVY/100222; Custom_Duty: 15%; Customs_HS_Code: 85423100; Distributor_name: NA; Distributor_part_number: NA; Footprint Path: Y:\MIS_DATABASE\Library\ALTIUM_TOOL\PCB_FOOTPRINTS\Altium_Footprint_Lib.PcbLib; Height: 1.00MM; Library Path: Y:\MIS_DATABASE\Library\ALTIUM_TOOL\SCHEMATICS_PARTS\MS_MISCPOWER_Library.schlib; Manufacturer: TEXAS INSTRUMENTS; Mfr_name: TEXAS INSTRUMENTS; Mistral Part No: 142022020015-R; Package: VQFNP40; Part_type: ICS\POWER\CONTROL; Project: TI_J7AHP_EVM_BRD; RoHS: RoHS; Temperature: -40°C+150°C; Tolerance: NA; Voltage: NA; Wattage: NA; Weight: NA; Datasheet: Y:\MIS_DATABASE\DATASHEETS\ICS\POWER\LM5143.PDF
U178 U180 = MOSFET_CSD17301Q5A: IC MOSFET N-CHANNEL NEXFET 60V VSONP8; Chkd/date: ALVY/240322; Crtd /date: TAMILARASU/220322; Custom_Duty: 15%; Customs_HS_Code: 85423100; Distributor_name: DIGIKEY; Distributor_part_number: 296-36511-1-ND; Footprint Path: Y:\MIS_DATABASE\Library\ALTIUM_TOOL\PCB_FOOTPRINTS\Altium_Footprint_Lib.PcbLib; Height: 1.10MM; Library Path: Y:\MIS_DATABASE\Library\ALTIUM_TOOL\SCHEMATICS_PARTS\MS_MOSFET_Library.schlib; Mfr_name: TEXAS INSTRUMENTS; Mistral Part No: 142022030018-R; Package: VSONP8; Part_type: ICS\POWER\MOSFET; Project: TI_J7AHP_EVM_BRD; RoHS: RoHS; Temperature: -55°C+150°C; Tolerance: NA; Voltage: NA; Wattage: NA; Weight: 86mg; Datasheet: Y:\MIS_DATABASE\DATASHEETS\ICS\POWER\CSD18563Q5A.PDF
C399 C439 C572 C588 C686 C1196 C1220 = CAP: CAP CERAMIC 0.01uF 50V 10% X7R 0402; Assembly_Instruction: DNI; Automotive Alternate_mfr_name: TDK; Automotive Alternate_mfr_part_number: CGA2B2X7R1E103K050BA; Chkd/date: MANIRAJA/280319; Crtd /date: MANIRAJA/280319; Custom_Duty: 15%; Customs_HS_Code: 85322990; Direct Alternate_mfr_name: YAGEO AMERICA; Direct Alternate_mfr_part_number: CC0402KRX7R8BB103; Distributor_name: DIGIKEY; Distributor_part_number: 490-4516-1-ND; Footprint Path: Y:\MIS_DATABASE\Library\ALTIUM_TOOL\PCB_FOOTPRINTS\Altium_Footprint_Lib.PcbLib; Height: 0.55MM; Library Path: Y:\MIS_DATABASE\Library\ALTIUM_TOOL\SCHEMATICS_PARTS\MS_DISCRETE_Library.schlib; Manufacturer: MURATA; Mfr_name: MURATA; Mfr_part_number: GRM155R71H103KA88D; Mistral Part No: 120009030025-R; Package: 0402; Part_type: CAPACITORS\CERAMIC; Project: G4_SVGA; RoHS: RoHS; Temperature: -55°C+125°C; Tolerance: 10%; Voltage: 50V; Wattage: NA; Weight: 0.65mg; Datasheet: Y:\MIS_DATABASE\DATASHEETS\CAPACITORS\GRM155R71H103KA88D.PDF
C408 C582 C584 C703 C1203 = CAP: CAP CERAMIC 4.7uF 25V 10% X6S 0603; Chkd/date: MANIRAJA/241018; Crtd /date: ALVY/241018; Custom_Duty: 15%; Customs_HS_Code: 85322990; Direct Alternate_mfr_name: MURATA; Direct Alternate_mfr_part_number: GRM188C81E475ME11D; Distributor_name: DIGIKEY; Distributor_part_number: 490-7199-1-ND; Footprint Path: Y:\MIS_DATABASE\Library\ALTIUM_TOOL\PCB_FOOTPRINTS\Altium_Footprint_Lib.PcbLib; Height: 1.00MM; Library Path: Y:\MIS_DATABASE\Library\ALTIUM_TOOL\SCHEMATICS_PARTS\MS_DISCRETE_Library.schlib; Manufacturer: MURATA; Mfr_name: MURATA; Mfr_part_number: GRM188C81E475KE11D; Mistral Part No: 120018100056-R; Package: 0603; Part_type: CAPACITORS\CERAMIC; Project: TI_J7ES_EVM_CP; RoHS: RoHS; Temperature: -55°C+105°C; Tolerance: 10%; Voltage: 25V; Wattage: NA; Weight: 6.3mg; Datasheet: Y:\MIS_DATABASE\DATASHEETS\CAPACITORS\GRM188C81E475KE11D.PDF
C409 C419 C464 C577 C583 C1176 C1200 C1209 = CAP: CAP CERAMIC 1uF 10V 10% X7S AUTO 0402; Automotive Alternate_mfr_name: TAIYO YUDEN; Automotive Alternate_mfr_part_number: EMK105BJ105KVHF; Chkd/date: MANIRAJA/100918; Crtd /date: ALVY/100918; Custom_Duty: 15%; Customs_HS_Code: 85322990; Direct Alternate_mfr_name: YAGEO AMERICA; Direct Alternate_mfr_part_number: CC0402KRX5R7BB105; Distributor_name: DIGIKEY; Distributor_part_number: 490-13409-1-ND; Footprint Path: Y:\MIS_DATABASE\Library\ALTIUM_TOOL\PCB_FOOTPRINTS\Altium_Footprint_Lib.PcbLib; Height: 0.70MM; Library Path: Y:\MIS_DATABASE\Library\ALTIUM_TOOL\SCHEMATICS_PARTS\MS_DISCRETE_Library.schlib; Manufacturer: TDK CORPORATION; Mfr_name: MURATA; Mfr_part_number: GCM155C71A105KE38D; Mistral Part No: 120018090021-R; Package: 0402; Part_type: CAPACITORS\CERAMIC; Project: SMART-M_SCRIPTALK_PB; RoHS: RoHS; Temperature: -55°C+125°C; Tolerance: 10%; Voltage: 10V; Wattage: NA; Weight: 6mg; Datasheet: Y:\MIS_DATABASE\DATASHEETS\CAPACITORS\MURATA-GCM-SER.PDF
C416 C461 C565 C580 C700 C1210 C1231 = CAP: CAP CERAMIC 10uF 16V 10% X5R 0805; Automotive Alternate_mfr_name: TDK; Automotive Alternate_mfr_part_number: CGA4J1X7S1C106K125AC; Chkd/date: SHREESHAIL/220506; Crtd /date: MAZHAR/150506; Custom_Duty: 15%; Customs_HS_Code: 85322990; Direct Alternate_mfr_name: TDK; Direct Alternate_mfr_part_number: C2012X7S1C106K125AC; Distributor_name: DIGIKEY; Distributor_part_number: 490-3886-1-ND; Footprint Path: Y:\MIS_DATABASE\Library\ALTIUM_TOOL\PCB_FOOTPRINTS\Altium_Footprint_Lib.PcbLib; Height: 1.35MM; Library Path: Y:\MIS_DATABASE\Library\ALTIUM_TOOL\SCHEMATICS_PARTS\MS_DISCRETE_Library.schlib; Manufacturer: MURATA; Mfr_name: MURATA; Mfr_part_number: GRM21BR61C106KE15L; Mistral Part No: 120009030205-R; Package: 0805; Part_type: CAPACITORS\CERAMIC; Project: VOCERA; RoHS: RoHS; Temperature: -55°C+85°C; Tolerance: 10%; Voltage: 16V; Wattage: NA; Weight: 9.5mg; Datasheet: Y:\MIS_DATABASE\DATASHEETS\CAPACITORS\MURATA-GXX-SER_NOV17.PDF
LD8 LD9 = LED_598-8170-107F: LED ALINGAP GREEN CLEAR 0805; Chkd/date: MANIRAJA/230817; Crtd /date: SARANYA/070514; Custom_Duty: 24%; Customs_HS_Code: 85437099; Distributor_name: DIGIKEY; Distributor_part_number: 350-2044-1-ND; Footprint Path: Y:\MIS_DATABASE\Library\ALTIUM_TOOL\PCB_FOOTPRINTS\Altium_Footprint_Lib.PcbLib; Height: 0.70MM; Manufacturer: DIALIGHT; Mfr_name: DIALIGHT; Mistral Part No: 130014050065-R; Package: 0805; Part_type: OPTO\LED; Project: AEGIS GP BETA2; RoHS: RoHS; Temperature: -30°C+85°C; Tolerance: NA; Voltage: NA; Wattage: NA; Weight: NA; Datasheet: Y:\MIS_DATABASE\DATASHEETS\DISCRETES\LEDS\598-SER.PDF
R207 R215 = RESISTOR: RES 220E 1/16W 1% 0402; Chkd/date: MANIRAJA/130917; Crtd /date: MANIRAJA/130917; Custom_Duty: 15%; Customs_HS_Code: 85332119; Distributor_name: DIGIKEY; Distributor_part_number: 311-220LRCT-ND; Footprint Path: Y:\MIS_DATABASE\Library\ALTIUM_TOOL\PCB_FOOTPRINTS\Altium_Footprint_Lib.PcbLib; Height: 0.40MM; Library Path: Y:\MIS_DATABASE\Library\ALTIUM_TOOL\SCHEMATICS_PARTS\MS_DISCRETE_Library.schlib; Manufacturer: YAGEO AMERICA; Mfr_name: YAGEO AMERICA; Mfr_part_number: RC0402FR-07220RL; Mistral Part No: 110019040169-R; Package: 0402; Part_type: RESISTORS\FIXED; Project: TI_SVB_MAXWELL_DUT; RoHS: RoHS; Temperature: -55°C+155°C; Tolerance: 1%; Voltage: NA; Wattage: 1/16W; Weight: 0.65mg; Datasheet: Y:\MIS_DATABASE\DATASHEETS\RESISTORS\RCXXXXL-SER_MAR18.PDF
R607 = RESISTOR: RES 4.53K 1/16W 1% 0402; Chkd/date: VASANTHA/201216; Crtd /date: USMAN/290709; Custom_Duty: 15%; Customs_HS_Code: 85332119; Distributor_name: DIGIKEY; Distributor_part_number: 541-4.53KLCT-ND; Footprint Path: Y:\MIS_DATABASE\Library\ALTIUM_TOOL\PCB_FOOTPRINTS\Altium_Footprint_Lib.PcbLib; Height: 0.40MM; Library Path: Y:\MIS_DATABASE\Library\ALTIUM_TOOL\SCHEMATICS_PARTS\MS_DISCRETE_Library.schlib; Manufacturer: VISHAY; Mfr_name: VISHAY; Mfr_part_number: CRCW04024K53FKED; Mistral Part No: 110016060008-R; Package: 0402; Part_type: RESISTORS\FIXED; Project: VMEFMCD; RoHS: RoHS; Temperature: -55°C+155°C; Tolerance: 1%; Voltage: NA; Wattage: 1/16W; Weight: 0.65mg; Datasheet: Y:\MIS_DATABASE\DATASHEETS\RESISTORS\CRCW0603.PDF
R611 = RESISTOR: RES 1.13K 1/16W 1% 0402; Chkd/date: MAZHAR/310709; Crtd /date: USMAN/300709; Custom_Duty: 15%; Customs_HS_Code: 85332119; Distributor_name: DIGIKEY; Distributor_part_number: 541-1.13KLCT-ND; Footprint Path: Y:\MIS_DATABASE\Library\ALTIUM_TOOL\PCB_FOOTPRINTS\Altium_Footprint_Lib.PcbLib; Height: 0.40MM; Library Path: Y:\MIS_DATABASE\Library\ALTIUM_TOOL\SCHEMATICS_PARTS\MS_DISCRETE_Library.schlib; Manufacturer: VISHAY; Mfr_name: VISHAY; Mfr_part_number: CRCW04021K13FKED; Mistral Part No: 110009070011-R; Package: 0402; Part_type: RESISTORS\FIXED; Project: VMEFMCD; RoHS: RoHS; Temperature: -55°C+155°C; Tolerance: 1%; Voltage: NA; Wattage: 1/16W; Weight: 0.65mg; Datasheet: Y:\MIS_DATABASE\DATASHEETS\RESISTORS\CRCW0603.PDF
R641 R1244 = RESISTOR: RES 1.69K 1/10W 1% 0402; Chkd/date: SHREESHAIL/121205; Crtd /date: MAZHAR/180705; Custom_Duty: 15%; Customs_HS_Code: 85332119; Distributor_name: DIGIKEY; Distributor_part_number: P1.69KLCT-ND; Footprint Path: Y:\MIS_DATABASE\Library\ALTIUM_TOOL\PCB_FOOTPRINTS\Altium_Footprint_Lib.PcbLib; Height: 0.40MM; Library Path: Y:\MIS_DATABASE\Library\ALTIUM_TOOL\SCHEMATICS_PARTS\MS_DISCRETE_Library.schlib; Manufacturer: PANASONIC-ECG; Mfr_name: PANASONIC-ECG; Mfr_part_number: ERJ-2RKF1691X; Mistral Part No: 110009030133-R; Package: 0402; Part_type: RESISTORS\FIXED; Project: PMP-VIOMEDIA; RoHS: RoHS; Temperature: -55°C+155°C; Tolerance: 1%; Voltage: NA; Wattage: 1/10W; Weight: 0.8mg; Datasheet: Y:\MIS_DATABASE\DATASHEETS\RESISTORS\PAN-ERJSER_NOV17.PDF
R643 R766 R791 R1248 = RESISTOR: RES 3.57K 1/16W 1% 0402; Chkd/date: VASANTHA/281216; Crtd /date: USMAN/300709; Custom_Duty: 15%; Customs_HS_Code: 85332119; Distributor_name: DIGIKEY; Distributor_part_number: 541-3.57KLCT-ND; Footprint Path: Y:\MIS_DATABASE\Library\ALTIUM_TOOL\PCB_FOOTPRINTS\Altium_Footprint_Lib.PcbLib; Height: 0.40MM; Library Path: Y:\MIS_DATABASE\Library\ALTIUM_TOOL\SCHEMATICS_PARTS\MS_DISCRETE_Library.schlib; Manufacturer: VISHAY; Mfr_name: VISHAY; Mfr_part_number: CRCW04023K57FKED; Mistral Part No: 110009070012-R; Package: 0402; Part_type: RESISTORS\FIXED; Project: VMEFMCD; RoHS: RoHS; Temperature: -55°C+155°C; Tolerance: 1%; Voltage: NA; Wattage: 1/16W; Weight: 0.65mg; Datasheet: Y:\MIS_DATABASE\DATASHEETS\RESISTORS\CRCW0603.PDF
R769 R793 = RESISTOR: RES 1.15K 1/16W 1% 0402; Chkd/date: MAZHAR/310709; Crtd /date: USMAN/300709; Custom_Duty: 15%; Customs_HS_Code: 85332119; Distributor_name: DIGIKEY; Distributor_part_number: 541-1.15KLCT-ND; Footprint Path: Y:\MIS_DATABASE\Library\ALTIUM_TOOL\PCB_FOOTPRINTS\Altium_Footprint_Lib.PcbLib; Height: 0.40MM; Library Path: Y:\MIS_DATABASE\Library\ALTIUM_TOOL\SCHEMATICS_PARTS\MS_DISCRETE_Library.schlib; Manufacturer: VISHAY; Mfr_name: VISHAY; Mfr_part_number: CRCW04021K15FKED; Mistral Part No: 110009070013-R; Package: 0402; Part_type: RESISTORS\FIXED; Project: VMEFMCD; RoHS: RoHS; Temperature: -55°C+155°C; Tolerance: 1%; Voltage: NA; Wattage: 1/16W; Weight: 0.65mg; Datasheet: Y:\MIS_DATABASE\DATASHEETS\RESISTORS\CRCW0603.PDF
R865 R1264 = RESISTOR: RES 4.99K 1/10W 1% 0402; Chkd/date: VASANTHA/281216; Crtd /date: MAZHAR/150506; Custom_Duty: 15%; Customs_HS_Code: 85332119; Distributor_name: DIGIKEY; Distributor_part_number: P4.99KLCT-ND; Footprint Path: Y:\MIS_DATABASE\Library\ALTIUM_TOOL\PCB_FOOTPRINTS\Altium_Footprint_Lib.PcbLib; Height: 0.40MM; Library Path: Y:\MIS_DATABASE\Library\ALTIUM_TOOL\SCHEMATICS_PARTS\MS_DISCRETE_Library.schlib; Manufacturer: PANASONIC-ECG; Mfr_name: PANASONIC-ECG; Mfr_part_number: ERJ-2RKF4991X; Mistral Part No: 110009030808-R; Package: 0402; Part_type: RESISTORS\FIXED; Project: VOCERA; RoHS: RoHS; Temperature: -55°C+155°C; Tolerance: 1%; Voltage: NA; Wattage: 1/10W; Weight: 0.8mg; Datasheet: Y:\MIS_DATABASE\DATASHEETS\RESISTORS\PAN-ERJSER_NOV17.PDF
R866 = RESISTOR: RES 2.49K 1/16W 1% 0402; Chkd/date: VASANTHA/270516; Crtd /date: VASANTHA/270516; Custom_Duty: 15%; Customs_HS_Code: 85332119; Distributor_name: DIGIKEY; Distributor_part_number: 311-2.49KLRCT-ND; Footprint Path: Y:\MIS_DATABASE\Library\ALTIUM_TOOL\PCB_FOOTPRINTS\Altium_Footprint_Lib.PcbLib; Height: 0.40MM; Library Path: Y:\MIS_DATABASE\Library\ALTIUM_TOOL\SCHEMATICS_PARTS\MS_DISCRETE_Library.schlib; Manufacturer: YAGEO AMERICA; Mfr_name: YAGEO AMERICA; Mfr_part_number: RC0402FR-072K49L; Mistral Part No: 110016050020-R; Package: 0402; Part_type: RESISTORS\FIXED; Project: TMDXCSKCC; RoHS: RoHS; Temperature: -55°C+155°C; Tolerance: 1%; Voltage: NA; Wattage: 1/16W; Weight: 0.65mg; Datasheet: Y:\MIS_DATABASE\DATASHEETS\RESISTORS\RCXXXXL-SER_MAR18.PDF
R1265 = RESISTOR: RES 1.87K 1/10W 1% 0402; Chkd/date: MAZHAR/151208; Crtd /date: USMAN/251108; Custom_Duty: 15%; Customs_HS_Code: 85332119; Distributor_name: DIGIKEY; Distributor_part_number: P1.87KLCT-ND; Footprint Path: Y:\MIS_DATABASE\Library\ALTIUM_TOOL\PCB_FOOTPRINTS\Altium_Footprint_Lib.PcbLib; Height: 0.40MM; Library Path: Y:\MIS_DATABASE\Library\ALTIUM_TOOL\SCHEMATICS_PARTS\MS_DISCRETE_Library.schlib; Manufacturer: PANASONIC-ECG; Mfr_name: PANASONIC-ECG; Mfr_part_number: ERJ-2RKF1871X; Mistral Part No: 110009030145-R; Package: 0402; Part_type: RESISTORS\FIXED; Project: KHAN_HSST; RoHS: RoHS; Temperature: -55°C+155°C; Tolerance: 1%; Voltage: NA; Wattage: 1/10W; Weight: 0.8mg; Datasheet: Y:\MIS_DATABASE\DATASHEETS\RESISTORS\PAN-ERJSER_NOV17.PDF
TP14 TP33 TP135 TP168 TP234 TP255 TP256 = TESTPOINT: TESTPOINT CIR 40 SMD; Chkd/date: MAZHAR/190505; Crtd /date: MAZHAR/190505; Distributor_name: NA; Distributor_part_number: NA; Footprint Path: Y:\MIS_DATABASE\Library\ALTIUM_TOOL\PCB_FOOTPRINTS\Altium_Footprint_Lib.PcbLib; Height: NA; Library Path: Y:\MIS_DATABASE\Library\ALTIUM_TOOL\SCHEMATICS_PARTS\MS_DISCRETE_Library.schlib; MECHANICAL 3D STEP FILE: NA; Manufacturer: LOCAL; Mfr_name: LOCAL; Mistral Part No: 130009030933; Package: SMD; Project: RAINIER-3; RoHS: NA; Temperature: NA; Tolerance: NA; Voltage: NA; Wattage: NA; Weight: NA; Datasheet: NA
TP28 TP240 TP249 = TESTPOINT: TESTPOINT 1.0MM DRILL PTH; Chkd/date: MAZHAR/271211; Crtd /date: SHREESHAIL/041005; Distributor_name: NA; Distributor_part_number: NA; Height: NA; Manufacturer: LOCAL; Mfr_name: LOCAL; Mistral Part No: 130009030938; Package: THRU-HOLE; Project: HSE; Datasheet: NA
TP207 TP211 = TESTPOINT: ACCESSORIE PC TEST POINT; Chkd/date: VASANTHA/121216; Crtd /date: MANIRAJA/121216; Custom_Duty: NA; Customs_HS_Code: NA; Distributor_name: DIGIKEY; Distributor_part_number: 36-5002-ND; Footprint Path: Y:\MIS_DATABASE\Library\ALTIUM_TOOL\PCB_FOOTPRINTS\Altium_Footprint_Lib.PcbLib; Height: 4.57MM; Library Path: Y:\MIS_DATABASE\Library\ALTIUM_TOOL\SCHEMATICS_PARTS\MS_DISCRETE_Library.schlib; Manufacturer: KEYSTONE; Mfr_name: KEYSTONE; Mistral Part No: 160016120008-R; Package: NA; Part_type: ACCESSORIES; Project: EPOS_EVM; RoHS: RoHS; Temperature: NA; Tolerance: NA; Voltage: NA; Wattage: NA; Weight: NA; Datasheet: Y:\MIS_DATABASE\DATASHEETS\MISC\ACCESSORIES\5002.PDF
U125 U138 U169 U174 U186 U260 U266 = TPS74801DRCR_SON10: IC 1.5A ADJUSTABLE LDO VOLTAGE REGULATOR WITH PROG SOFT-START VSON10; Automotive Alternate_mfr_name: TEXAS INSTRUMENTS; Automotive Alternate_mfr_part_number: TPS74801TDRCRQ1; Chkd/date: MANIRAJA/190218; Crtd /date: USMAN/191208; Custom_Duty: 15%; Customs_HS_Code: 85423100; Distributor_name: DIGIKEY; Distributor_part_number: 296-21563-1-ND; Footprint Path: Y:\MIS_DATABASE\Library\ALTIUM_TOOL\PCB_FOOTPRINTS\Altium_Footprint_Lib.PcbLib; Height: 1.00MM; Library Path: Y:\MIS_DATABASE\Library\ALTIUM_TOOL\SCHEMATICS_PARTS\MS_MISCPOWER_Library.schlib; Manufacturer: TEXAS INSTRUMENTS; Mfr_name: TEXAS INSTRUMENTS; Mistral Part No: 142009030403-R; Package: VSON10; Part_type: ICS\POWER\VOLTAGE REGULATOR; Project: BSN-II; RoHS: RoHS; Temperature: -40°C+125°C; Tolerance: NA; Voltage: NA; Wattage: NA; Weight: 26.1mg; Datasheet: Y:\MIS_DATABASE\DATASHEETS\MISC\REGULATORS\TPS748XX.PDF

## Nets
DGND: C58.1 C82.1 C84.2 C88.2 C92.2 C95.2 C101.2 C103.2 C106.2 C108.1 C111.1 C112.2 C114.1 C116.2 C117.2 C120.2 C123.2 C124.2 C126.2 C399.2 C408.1 C409.2 C416.2 C417.1 C418.1 C419.2 C439.2 C461.2 C462.1 C463.1 C464.2 C565.2 C570.1 C572.2 C577.2 C578.1 C579.1 C580.2 C581.1 C582.1 C583.2 C584.1 C588.2 C629.2 C686.2 C700.2 C701.1 C702.1 C703.1 C1176.2 C1182.1 C1196.2 C1200.2 C1203.1 C1204.1 C1206.1 C1209.2 C1210.2 C1220.2 C1228.1 C1231.2 LD8.1 LD9.1 R133.2 R607.2 R641.2 R769.2 R786.2 R793.2 R798.2 R816.2 R833.1 R865.2 R1244.2 R1264.2 TP14.1(TP) TP28.1(TP) TP33.1(TP) TP135.1(TP) TP168.1(TP) TP207.1(TP) TP211.1(TP) TP249.1(TP) U24.1(S1) U24.2(S2) U24.3(S3) U25.3(FB2) U25.14(PGND2) U25.17(PGND1) U25.35(AGND) U25.41(EP) U27.1(S1) U27.2(S2) U27.3(S3) U125.6(GND) U125.11(PAD) U138.6(GND) U138.11(PAD) U169.6(GND) U169.11(PAD) U174.6(GND) U174.11(PAD) U186.6(GND) U186.11(PAD) U260.6(GND) U260.11(PAD) U266.6(GND) U266.11(PAD) ; also on sheet 11 12 13 14 15 16 17 18 20 21 22 23 24 25 26 27 28 29 30 31 32 33 34 35 36 37 38 39 40 41 42 43 44 45 46 47 48 49 50 51 52 53 54 55 56 57 58 59 60 61 62 63 64 65 66 69 70 71 72 73 76 77 78 79 81 82 83 84
V3V3_DP0: C579.2 C580.1 R791.1 TP256.1(TP) U174.9(OUT1) U174.10(OUT2) ; also on sheet 57
V3V3_DP1: C565.1 C570.2 R766.1 TP255.1(TP) U169.9(OUT1) U169.10(OUT2) ; also on sheet 57
VCC_1V1: C1228.2 C1231.1 R1265.1 TP240.1(TP) U266.9(OUT1) U266.10(OUT2) ; also on sheet 51 56
VCC_1V2: C700.1 C701.2 R866.1 R875.1 TP259.1(TP) U186.9(OUT1) U186.10(OUT2) ; also on sheet 42 61
VCC_LM5143: C108.2 C114.2 D31.2(ANODE) D32.2(ANODE) U25.15(VCC) U25.16(VCC)
VDD_1V0: C416.1 C417.2 R611.1 TP219.1(TP) U125.9(OUT1) U125.10(OUT2) ; also on sheet 55
VDD_2V5: C1204.2 C1210.1 R1207.1 R1248.1 TP232.1(TP) U260.9(OUT1) U260.10(OUT2) ; also on sheet 56
VDD_MCU_2V5: C461.1 C462.2 R643.1 R648.1 TP234.1(TP) U138.9(OUT1) U138.10(OUT2) ; also on sheet 55
VDDA_LM5143: C111.2 R832.1 U25.33(DEMB) U25.34(MODE) U25.36(VDDA)
VINPUT: C92.1 C106.1 C116.1 C124.1 R125.2 R148.2 U25.25(VIN) U178.5(D) U180.5(D) ; also on sheet 36 64 65 66
COMP1_LM5143: C95.1 R117.2 U25.2(COMP2) U25.29(COMP1)
CS1_LM5143: C121.2 R151.2 U25.27(CS1)
CS2_LM5143: C94.1 R111.2 U25.4(CS2)
DP0_PWR_SW_EN: R798.1 U174.5(EN) ; also on sheet 38
DP1_PWR_SW_EN: R786.1 U169.5(EN) ; also on sheet 38
EN1_LM5143: R148.1 U25.31(EN1)
EN2_LM5143: R125.1 U25.40(EN2)
FB_MCU_V2V5: R641.1 R643.2 U138.8(FB)
FB_V1V0: R607.1 R611.2 U125.8(FB)
FB_V1V1: R1264.1 R1265.2 U266.8(FB)
FB_V1V2: R865.1 R866.2 U186.8(FB)
FB_V2V5: R1244.1 R1248.2 U260.8(FB)
FB_V3V3_DP0: R791.2 R793.1 U174.8(FB)
FB_V3V3_DP1: R766.2 R769.1 U169.8(FB)
LM5143_FB: R832.2 R833.2 R834.2 U25.28(FB1)
LM5143_HB1: C122.2 D32.1(CATHODE) U25.20(HB1)
LM5143_HB2: C100.1 D31.1(CATHODE) U25.11(HB2)
LM5143_HO1: R149.2 U25.22(HO1)
LM5143_HO2: R118.1 U25.9(HO2)
LM5143_HOL1: R149.1 U25.23(HOL1) U180.4(G)
LM5143_HOL2: R118.2 U25.8(HOL2) U178.4(G)
LM5143_LO1: U25.18(LO1) U25.19(LOL1) U27.4(G)
LM5143_LO2: U24.4(G) U25.12(LOL2) U25.13(LO2)
LM5143_PG1: R828.1 U25.24(PG1) ; also on sheet 36
LM5143_PG2: R817.1 U25.7(PG2) ; also on sheet 36
LM5143_SW1: C122.1 L22.2 U25.21(SW1) U27.5(D) U180.1(S1) U180.2(S2) U180.3(S3)
LM5143_SW2: C100.2 L21.1 U24.5(D) U25.10(SW2) U178.1(S1) U178.2(S2) U178.3(S3)
PG_MCU_V2V5: R648.2 U125.5(EN) U138.3(PG)
PG_V1V2: R875.2 U186.3(PG)
PG_V2V5: R1207.2 U260.3(PG)
RES_LM5143: C117.1 U25.32(RES)
SS1_LM5143: C123.1 U25.1(SS2) U25.30(SS1)
SYNOUT_LM5143: TP23.1(TP) U25.39(SYNCOUT)
V_3V3: C58.2 C82.2 C84.1 C101.1 C112.1 C120.1 C126.1 C629.1 R53.2 R110.2 R136.1 R136.3 R150.2 R165.1
VSYS_3V3: C408.2 C418.2 C419.1 C463.2 C464.1 C702.2 C703.2 C1176.1 C1182.2 C1200.1 C1203.2 C1206.2 R136.4 R136.6 R817.2 R828.2 R834.1 U125.1(IN1) U125.2(IN2) U125.4(BIAS) U138.1(IN1) U138.2(IN2) U186.1(IN1) U186.2(IN2) U186.4(BIAS) U260.1(IN1) U260.2(IN2) U266.1(IN1) U266.2(IN2) U266.4(BIAS) ; also on sheet 22 23 35 36 40 47 49 62 63 65 66 69 73 75 76 77 78 79
VSYS_3V3_N: R136.5 ; also on sheet 77
VSYS_3V3_P: R136.2 ; also on sheet 77
VSYS_5V0: C409.1 C577.1 C578.2 C581.2 C582.2 C583.1 C584.2 U169.1(IN1) U169.2(IN2) U169.4(BIAS) U174.1(IN1) U174.2(IN2) U174.4(BIAS) U260.4(BIAS) ; also on sheet 20 30 31 50 52 59 65 72 81 82 83 84
VSYS_IO_3V3: R215.1 R863.1 R1208.1 R1242.1 ; also on sheet 18 20 22 24 29 30 31 32 33 35 36 37 38 40 41 42 43 45 46 48 50 51 53 56 57 58 59 60 61 65 66 75 81 82
VSYS_MCU_5V0: C1209.1 U138.4(BIAS) ; also on sheet 49
VSYS_MCUIO_3V3: R207.1 R639.1 ; also on sheet 16 17 18 21 22 23 35 36 43 44 48 49 55 62 65 75
N24016673: C439.1 U138.7(SS)
N24017280: C1220.1 U266.7(SS)
N24397394: C588.1 U174.7(SS)
N24401396: C572.1 U169.7(SS)
N25567208: R639.2 U138.5(EN)
N25567428: R1242.2 U266.5(EN)
N34888044: L21.2 R53.1 R111.1
N34888058: C94.2 R110.1 U25.5(VOUT2)
N34888105: L22.1 R151.1 R165.2
N34888129: C121.1 R150.1 U25.26(VOUT1)
N35193628: R1208.2 U260.5(EN)
N35193714: C1196.1 U260.7(SS)
N35201087: C399.1 U125.7(SS)
N35210314: R133.1 U25.37(RT)
N35214365: R816.1 U25.6(VCCX)
N35215938: C88.1 R117.1
N35218154: C103.1 U25.38(DITH)
N36263992: R863.2 U186.5(EN)
N36264078: C686.1 U186.7(SS)
N42762976: LD9.2 R215.2
N42762977: LD8.2 R207.2

Not connected (* = marked no-connect by the designer): U125 3(PG)*; U169 3(PG)*; U174 3(PG)*; U266 3(PG)*

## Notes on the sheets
sheet 67
- POWER SUPPLY #1
sheet 68
- POWER SUPPLY #4
- ETHERNET POWER- MCU RGMII
- Display Port0
- Vout=2.5V
  Iout=137mA
- 5V to 3.3V LDO
- Vout=3.3V
  Iout=500mA
- 3.3V to 2.5V LDO
- PCB NOTE:Keep 4.7uF capacitor close to BIAS pin.
  Keep this circuit close to DP PORT0 Connector
- 3.3V to 1.0V LDO
- Display Port1
- Vout=1V
  Iout=108mA
- 5V to 3.3V LDO
- Vout=3.3V
  Iout=500mA
- PCB NOTE:Keep 4.7uF capacitor close BIAS pin
- ETHERNET POWER- RGMII1
- Vout=2.5V
  Iout=137mA
- 3.3V to 2.5V LDO
- PCB NOTE:Keep 4.7uF capacitor close to BIAS pin.
  Keep this circuit close to DP PORT1 Connector.
- 3.3V to 1.2V LDO
- Vout=1.2V
  Iout=900mA
- POWER INDICATION LED's
- USB HUB POWER & ETHERNET POWER - RGMII1
- 3.3V to 1.1V LDO
- silkscreen:"VSYS_IO_3V3"
- silkscreen:"MUCIO_3V3"
- Vout=1.1V
  Iout=302mA
- SOC PWR LED
- MCU PWR LED
- GROUND TEST POINTS
- PCB NOTE: Spread the SMD
  test points Top and Bottom
  Side of PCB
- PCB NOTE:Keep 4.7uF capacitor close BIAS pin
